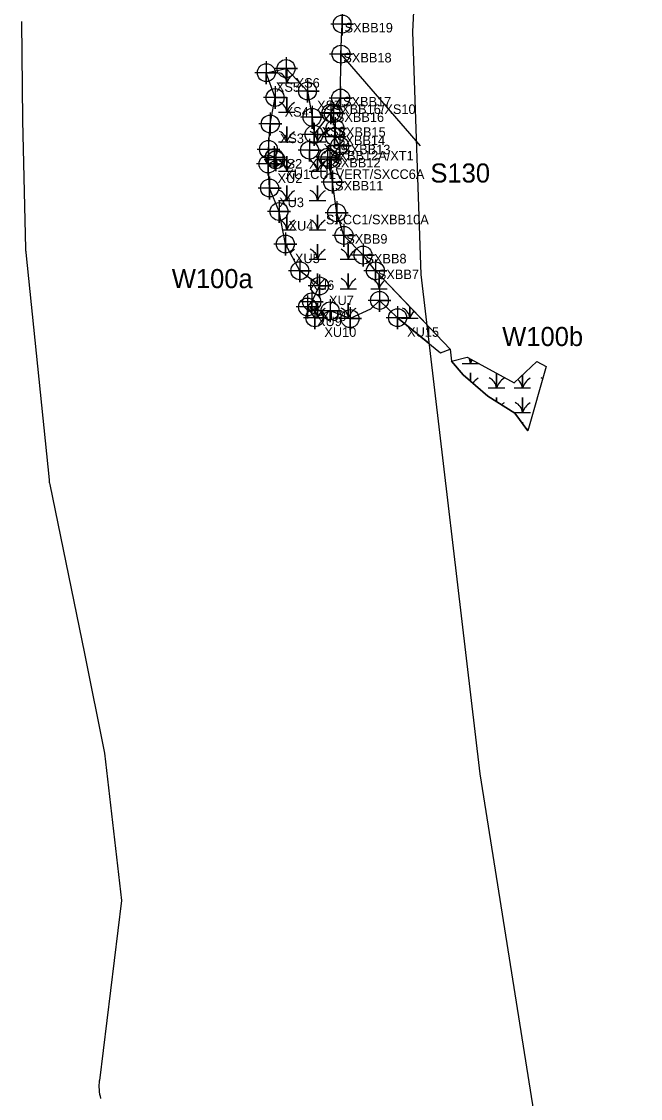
# Model space of a CAD drawing. Extents: x 1253697 to 1278588, y 912189 to 981699.
# Drawn here: x 1268749 to 1269397, y 969005 to 970132 of the extents above; entities that cross this region are included whole.
import ezdxf

# ---------------------------------------------------------------- set-up
doc = ezdxf.new("R2010")
doc.units = 0
for name, color, linetype in [('Default', 7, 'Continuous'), ('Exist Environmental Wetland Boundary', 7, 'Continuous'), ('Exist Environmental Wetland Boundary Cogo Comment', 7, 'Continuous'), ('Exist Environmental Wetland Boundary Cogo Number', 7, 'Continuous'), ('Exist Environmental Wetland Boundary Cogo Point CELL', 7, 'Continuous'), ('Exist Hydro Jurisdictional Stream or Body of Water Mitigable', 7, 'Continuous'), ('Exist Hydro Jurisdictional Stream or Body of Water Mitigable Cogo Comment', 7, 'Continuous'), ('Exist Hydro Jurisdictional Stream or Body of Water Mitigable Cogo Number', 7, 'Continuous'), ('Exist Hydro Jurisdictional Stream or Body of Water Mitigable Cogo Point CELL', 7, 'Continuous'), ('Exist Hydro Swamp or Marsh', 7, 'Continuous')]:
    doc.layers.add(name, color=color, linetype=linetype)

msp = doc.modelspace()

# ---------------------------------------------------------------- linework, layer by layer
at = {"layer": 'Default'}
for p, q in [((1268748.9, 970131.8), (1268749.9, 970028.8)), ((1268748.9, 970131.8), (1268749.9, 970028.8)), ((1269083.5, 970097.7), (1269166.6, 970001.9)), ((1268750, 970028.1), (1268753.1, 969894)), ((1268750, 970028.1), (1268753.1, 969894)), ((1268753.4, 969890.2), (1268777.7, 969652.3)), ((1268753.4, 969890.2), (1268777.7, 969652.3))]:
    msp.add_line(p, q, dxfattribs=at)
for points in [[(1269397.3, 968290), (1269229.4, 969344.4), (1269167.4, 969867.2), (1269158.7, 970121), (1269167.3, 970291.9), (1269169.1, 970315.5)], [(1269397.3, 968290), (1269229.4, 969344.4), (1269167.4, 969867.2), (1269158.7, 970121), (1269167.3, 970291.9), (1269169.1, 970315.5)], [(1268778.5, 969647.3), (1268814.9, 969470.3), (1268835.9, 969366.2), (1268853.5, 969211.8), (1268830.4, 969023.6)], [(1268778.5, 969647.3), (1268814.9, 969470.3), (1268835.9, 969366.2), (1268853.5, 969211.8), (1268830.4, 969023.6)]]:
    msp.add_lwpolyline(points, dxfattribs=at)
for centre, start, end in [((1268799.9, 970029.3), 180.6032, 181.3602), ((1268799.9, 970029.3), 180.6032, 181.3602), ((1268803.1, 969895.2), 181.3602, 185.8348), ((1268803.1, 969895.2), 181.3602, 185.8348), ((1268827.4, 969657.4), 185.8348, 191.6336), ((1268827.4, 969657.4), 185.8348, 191.6336), ((1268880, 969017.5), 172.9863, 194.8089), ((1268880, 969017.5), 172.9863, 194.8089)]:
    msp.add_arc(centre, 50, start, end, dxfattribs=at)
at = {"layer": 'Exist Environmental Wetland Boundary'}
for p, q in [((1269292.2, 969774.1), (1269292.3, 969774.1)), ((1269227.3, 969748.3), (1269227.8, 969748.3))]:
    msp.add_line(p, q, dxfattribs=at)
for points in [[(1269007.1, 969982.8), (1269007.6, 969998), (1269009.4, 970024.6), (1269014.5, 970052.3), (1269005.3, 970078.3), (1269026, 970082.6), (1269048.5, 970059.1), (1269053.2, 970031.6), (1269055.3, 970013.7), (1269073, 970036.3)], [(1269176, 969794.8), (1269142.8, 969821.9), (1269123.9, 969840), (1269114.3, 969830.9), (1269093, 969820.9), (1269072.1, 969829.1), (1269056.1, 969821.8), (1269048.4, 969833.1), (1269052.9, 969838.4), (1269061, 969855.1), (1269040.4, 969871), (1269025.3, 969899), (1269018.6, 969933), (1269008.7, 969957.6), (1269007.1, 969982.8), (1269015.2, 969987.1)], [(1269142.8, 969821.9), (1269187.9, 969785.1), (1269197.8, 969789), (1269119.6, 969870.9)], [(1269210.6, 969774.1), (1269219.2, 969774.1), (1269219.2, 969778.7)], [(1269219.2, 969778.7), (1269219.2, 969774.1), (1269227.7, 969774.1)], [(1269219.2, 969755.4), (1269219.2, 969764.1), (1269219.2, 969755.4)], [(1269237.8, 969748.3), (1269246.4, 969748.3), (1269246.4, 969763.9)], [(1269246.4, 969763.9), (1269246.4, 969748.3), (1269255, 969748.3)], [(1269265, 969748.3), (1269273.6, 969748.3), (1269273.6, 969761.9)], [(1269273.6, 969761.9), (1269273.6, 969748.3), (1269282.2, 969748.3)], [(1269246.4, 969733.9), (1269246.4, 969738.3), (1269246.4, 969733.9)], [(1269265, 969722.5), (1269273.6, 969722.5), (1269273.6, 969738.3), (1269273.6, 969722.5), (1269282.2, 969722.5)], [(1269273.6, 969711), (1269273.6, 969712.5), (1269273.6, 969711)]]:
    msp.add_lwpolyline(points, dxfattribs=at)
msp.add_lwpolyline([(1269199.4, 969776.3), (1269215.7, 969780.6), (1269264.8, 969753.8), (1269288.8, 969775.9), (1269298.4, 969770.9), (1269279.2, 969703.5), (1269265.6, 969721.9), (1269237.2, 969739.7), (1269211.6, 969762.1)], close=True, dxfattribs=at)
for centre, radius, start, end in [((1269206.9, 969773.2), 12.3, 4.1403, 32.0357), ((1269237.4, 969768), 19.2, 149.4542, 161.6222), ((1269237.4, 969742.2), 19.2, 122.1274, 145.031), ((1269234.1, 969747.4), 12.3, 4.1403, 67.535), ((1269264.6, 969742.2), 19.2, 122.1274, 161.6222), ((1269261.3, 969747.4), 12.3, 4.1403, 53.5689), ((1269291.9, 969742.2), 19.2, 122.1274, 161.6222), ((1269288.5, 969747.4), 12.3, 59.7157, 67.535), ((1269264.6, 969716.5), 19.2, 122.1274, 132.5441), ((1269261.3, 969721.6), 12.3, 4.1403, 67.535), ((1269291.9, 969716.5), 19.2, 122.1274, 161.6222), ((1269291.9, 969690.7), 19.2, 128.7859, 134.1878)]:
    msp.add_arc(centre, radius, start, end, dxfattribs=at)
at = {"layer": 'Exist Environmental Wetland Boundary Cogo Point CELL'}
for points in [[(1269005.3, 970090.3), (1269005.3, 970066.3), (1269005.3, 970078.3), (1269017.3, 970078.3), (1268993.3, 970078.3)], [(1269026, 970094.6), (1269026, 970070.6), (1269026, 970082.6), (1269038, 970082.6), (1269014, 970082.6)], [(1269014.5, 970064.3), (1269014.5, 970040.3), (1269014.5, 970052.3), (1269026.5, 970052.3), (1269002.5, 970052.3)], [(1269048.5, 970071.1), (1269048.5, 970047.1), (1269048.5, 970059.1), (1269060.5, 970059.1), (1269036.5, 970059.1)], [(1269053.2, 970043.6), (1269053.2, 970019.6), (1269053.2, 970031.6), (1269065.2, 970031.6), (1269041.2, 970031.6)], [(1269009.4, 970036.6), (1269009.4, 970012.6), (1269009.4, 970024.6), (1269021.4, 970024.6), (1268997.4, 970024.6)], [(1269055.3, 970025.7), (1269055.3, 970001.7), (1269055.3, 970013.7), (1269067.3, 970013.7), (1269043.3, 970013.7)], [(1269007.6, 970010), (1269007.6, 969986), (1269007.6, 969998), (1269019.6, 969998), (1268995.6, 969998)], [(1269050.6, 970009.2), (1269050.6, 969985.2), (1269050.6, 969997.2), (1269062.6, 969997.2), (1269038.6, 969997.2)], [(1269007.1, 969994.8), (1269007.1, 969970.8), (1269007.1, 969982.8), (1269019.1, 969982.8), (1268995.1, 969982.8)], [(1269013.5, 970001.5), (1269013.5, 969977.5), (1269013.5, 969989.5), (1269025.5, 969989.5), (1269001.5, 969989.5)], [(1269015.2, 969999.1), (1269015.2, 969975.1), (1269015.2, 969987.1), (1269027.2, 969987.1), (1269003.2, 969987.1)], [(1269008.7, 969969.6), (1269008.7, 969945.6), (1269008.7, 969957.6), (1269020.7, 969957.6), (1268996.7, 969957.6)], [(1269018.6, 969945), (1269018.6, 969921), (1269018.6, 969933), (1269030.6, 969933), (1269006.6, 969933)], [(1269025.3, 969911), (1269025.3, 969887), (1269025.3, 969899), (1269037.3, 969899), (1269013.3, 969899)], [(1269040.4, 969883), (1269040.4, 969859), (1269040.4, 969871), (1269052.4, 969871), (1269028.4, 969871)], [(1269061, 969867.1), (1269061, 969843.1), (1269061, 969855.1), (1269073, 969855.1), (1269049, 969855.1)], [(1269052.9, 969850.4), (1269052.9, 969826.4), (1269052.9, 969838.4), (1269064.9, 969838.4), (1269040.9, 969838.4)], [(1269123.9, 969852), (1269123.9, 969828), (1269123.9, 969840), (1269135.9, 969840), (1269111.9, 969840)], [(1269048.4, 969845.1), (1269048.4, 969821.1), (1269048.4, 969833.1), (1269060.4, 969833.1), (1269036.4, 969833.1)], [(1269072.1, 969841.1), (1269072.1, 969817.1), (1269072.1, 969829.1), (1269084.1, 969829.1), (1269060.1, 969829.1)], [(1269056.1, 969833.8), (1269056.1, 969809.8), (1269056.1, 969821.8), (1269068.1, 969821.8), (1269044.1, 969821.8)], [(1269093, 969832.9), (1269093, 969808.9), (1269093, 969820.9), (1269105, 969820.9), (1269081, 969820.9)], [(1269142.8, 969833.9), (1269142.8, 969809.9), (1269142.8, 969821.9), (1269154.8, 969821.9), (1269130.8, 969821.9)]]:
    msp.add_lwpolyline(points, dxfattribs=at)
for centre in [(1269005.3, 970078.3), (1269026, 970082.6), (1269014.5, 970052.3), (1269048.5, 970059.1), (1269053.2, 970031.6), (1269009.4, 970024.6), (1269055.3, 970013.7), (1269007.6, 969998), (1269050.6, 969997.2), (1269013.5, 969989.5), (1269015.2, 969987.1), (1269007.1, 969982.8), (1269008.7, 969957.6), (1269018.6, 969933), (1269025.3, 969899), (1269040.4, 969871), (1269061, 969855.1), (1269052.9, 969838.4), (1269123.9, 969840), (1269048.4, 969833.1), (1269072.1, 969829.1), (1269056.1, 969821.8), (1269093, 969820.9), (1269142.8, 969821.9)]:
    msp.add_circle(centre, 9.38, dxfattribs=at)
at = {"layer": 'Exist Hydro Jurisdictional Stream or Body of Water Mitigable'}
for points in [[(1269173.7, 969814.3), (1269119.6, 969870.9), (1269106.6, 969887.4), (1269086.6, 969908), (1269079, 969931.7), (1269074.8, 969963.8), (1269071.9, 969987.9), (1269082.2, 970001.7), (1269076.7, 970011.2), (1269077.3, 970019.9), (1269073, 970036.3), (1269083.1, 970051.7), (1269083.5, 970097.7), (1269084.8, 970129.2), (1269085.3, 970162.5)], [(1269119.6, 969870.9), (1269197.8, 969789), (1269199.4, 969776.3), (1269211.6, 969762.1), (1269237.2, 969739.7), (1269265.6, 969721.9), (1269279.2, 969703.5)]]:
    msp.add_lwpolyline(points, dxfattribs=at)
at = {"layer": 'Exist Hydro Jurisdictional Stream or Body of Water Mitigable Cogo Point CELL'}
for points in [[(1269084.8, 970141.2), (1269084.8, 970117.2), (1269084.8, 970129.2), (1269096.8, 970129.2), (1269072.8, 970129.2)], [(1269083.5, 970109.7), (1269083.5, 970085.7), (1269083.5, 970097.7), (1269095.5, 970097.7), (1269071.5, 970097.7)], [(1269083.1, 970063.7), (1269083.1, 970039.7), (1269083.1, 970051.7), (1269095.1, 970051.7), (1269071.1, 970051.7)], [(1269073, 970048.3), (1269073, 970024.3), (1269073, 970036.3), (1269085, 970036.3), (1269061, 970036.3)], [(1269075.6, 970047.5), (1269075.6, 970023.5), (1269075.6, 970035.5), (1269087.6, 970035.5), (1269063.6, 970035.5)], [(1269077.3, 970031.9), (1269077.3, 970007.9), (1269077.3, 970019.9), (1269089.3, 970019.9), (1269065.3, 970019.9)], [(1269076.7, 970023.2), (1269076.7, 969999.2), (1269076.7, 970011.2), (1269088.7, 970011.2), (1269064.7, 970011.2)], [(1269082.2, 970013.7), (1269082.2, 969989.7), (1269082.2, 970001.7), (1269094.2, 970001.7), (1269070.2, 970001.7)], [(1269069.5, 970001.8), (1269069.5, 969977.8), (1269069.5, 969989.8), (1269081.5, 969989.8), (1269057.5, 969989.8)], [(1269071.9, 969999.9), (1269071.9, 969975.9), (1269071.9, 969987.9), (1269083.9, 969987.9), (1269059.9, 969987.9)], [(1269074.8, 969975.8), (1269074.8, 969951.8), (1269074.8, 969963.8), (1269086.8, 969963.8), (1269062.8, 969963.8)], [(1269079, 969943.7), (1269079, 969919.7), (1269079, 969931.7), (1269091, 969931.7), (1269067, 969931.7)], [(1269086.6, 969920), (1269086.6, 969896), (1269086.6, 969908), (1269098.6, 969908), (1269074.6, 969908)], [(1269106.6, 969899.4), (1269106.6, 969875.4), (1269106.6, 969887.4), (1269118.6, 969887.4), (1269094.6, 969887.4)], [(1269119.6, 969882.9), (1269119.6, 969858.9), (1269119.6, 969870.9), (1269131.6, 969870.9), (1269107.6, 969870.9)]]:
    msp.add_lwpolyline(points, dxfattribs=at)
for centre in [(1269084.8, 970129.2), (1269083.5, 970097.7), (1269083.1, 970051.7), (1269073, 970036.3), (1269075.6, 970035.5), (1269077.3, 970019.9), (1269076.7, 970011.2), (1269082.2, 970001.7), (1269069.5, 969989.8), (1269071.9, 969987.9), (1269074.8, 969963.8), (1269079, 969931.7), (1269086.6, 969908), (1269106.6, 969887.4), (1269119.6, 969870.9)]:
    msp.add_circle(centre, 9.38, dxfattribs=at)
at = {"layer": 'Exist Hydro Swamp or Marsh'}
for p, q in [((1269050.3, 970036.9), (1269052.3, 970036.9)), ((1269082.5, 969913.8), (1269084.8, 969913.8)), ((1269033.9, 969883), (1269035.3, 969883)), ((1269059.6, 969852.2), (1269067.5, 969852.2)), ((1269091.7, 969821.5), (1269094.1, 969821.5))]:
    msp.add_line(p, q, dxfattribs=at)
for points in [[(1269018.1, 970067.7), (1269026.7, 970067.7), (1269026.7, 970081.8)], [(1269026.7, 970081.8), (1269026.7, 970067.7), (1269035.3, 970067.7)], [(1269018.1, 970036.9), (1269026.7, 970036.9), (1269026.7, 970052.7), (1269026.7, 970036.9), (1269035.3, 970036.9)], [(1269018.1, 970006.1), (1269026.7, 970006.1), (1269026.7, 970021.9), (1269026.7, 970006.1), (1269035.3, 970006.1)], [(1269050.3, 970006.1), (1269058.9, 970006.1), (1269058.9, 970018.4)], [(1269058.9, 970018.4), (1269058.9, 970006.1), (1269067.5, 970006.1)], [(1269018.1, 969975.4), (1269026.7, 969975.4), (1269026.7, 969991.1), (1269026.7, 969975.4), (1269035.3, 969975.4)], [(1269050.3, 969975.4), (1269058.9, 969975.4), (1269058.9, 969991.1), (1269058.9, 969975.4), (1269067.5, 969975.4)], [(1269018.1, 969944.6), (1269026.7, 969944.6), (1269026.7, 969960.4), (1269026.7, 969944.6), (1269035.3, 969944.6)], [(1269050.3, 969944.6), (1269058.9, 969944.6), (1269058.9, 969960.4), (1269058.9, 969944.6), (1269067.5, 969944.6)], [(1269022.4, 969913.8), (1269026.7, 969913.8), (1269026.7, 969929.6), (1269026.7, 969913.8), (1269035.3, 969913.8)], [(1269050.3, 969913.8), (1269058.9, 969913.8), (1269058.9, 969929.6), (1269058.9, 969913.8), (1269067.5, 969913.8)], [(1269026.7, 969896.3), (1269026.7, 969898.8), (1269026.7, 969896.3)], [(1269050.3, 969883), (1269058.9, 969883), (1269058.9, 969898.8), (1269058.9, 969883), (1269067.5, 969883)], [(1269082.5, 969883), (1269091.1, 969883), (1269091.1, 969898.8), (1269091.1, 969883), (1269099.7, 969883)], [(1269058.9, 969856.7), (1269058.9, 969868), (1269058.9, 969856.7)], [(1269082.5, 969852.2), (1269091.1, 969852.2), (1269091.1, 969868), (1269091.1, 969852.2), (1269099.7, 969852.2)], [(1269114.7, 969852.2), (1269123.4, 969852.2), (1269123.4, 969867)], [(1269123.4, 969867), (1269123.4, 969852.2), (1269132, 969852.2)], [(1269058.9, 969823.1), (1269058.9, 969837.2), (1269058.9, 969823.1)], [(1269091.1, 969821.7), (1269091.1, 969837.2), (1269091.1, 969821.7)], [(1269147, 969821.5), (1269155.6, 969821.5), (1269155.6, 969833.3)], [(1269155.6, 969833.3), (1269155.6, 969821.5), (1269164.2, 969821.5)]]:
    msp.add_lwpolyline(points, dxfattribs=at)
for centre, radius, start, end in [((1269014.5, 970066.8), 12.3, 4.1403, 67.535), ((1269045, 970061.6), 19.2, 131.4132, 161.6222), ((1269014.5, 970036), 12.3, 4.1403, 67.535), ((1269045, 970030.9), 19.2, 122.1274, 161.6222), ((1269014.5, 970005.3), 12.3, 4.1403, 67.535), ((1269045, 970000.1), 19.2, 122.1274, 161.6222), ((1269046.7, 970005.3), 12.3, 46.0042, 67.535), ((1269077.2, 970000.1), 19.2, 122.1274, 161.6222), ((1269046.7, 970005.3), 12.3, 4.1403, 44.674), ((1269014.5, 969974.5), 12.3, 4.1403, 67.535), ((1269045, 969969.3), 19.2, 122.1274, 161.6222), ((1269046.7, 969974.5), 12.3, 4.1403, 67.535), ((1269077.2, 969969.3), 19.2, 122.1274, 161.6222), ((1269014.5, 969943.7), 12.3, 4.1403, 67.535), ((1269045, 969938.5), 19.2, 122.1274, 161.6222), ((1269046.7, 969943.7), 12.3, 4.1403, 67.535), ((1269077.2, 969938.5), 19.2, 122.1274, 161.6222), ((1269014.5, 969912.9), 12.3, 4.1403, 60.802), ((1269045, 969907.7), 19.2, 122.1274, 161.6222), ((1269046.7, 969912.9), 12.3, 4.1403, 67.535), ((1269077.2, 969907.7), 19.2, 122.1274, 161.6222), ((1269045, 969877), 19.2, 122.1274, 139.2433), ((1269046.7, 969882.1), 12.3, 4.1403, 67.535), ((1269077.2, 969877), 19.2, 122.1274, 161.6222), ((1269078.9, 969882.1), 12.3, 4.1403, 67.535), ((1269109.4, 969877), 19.2, 122.1274, 161.6222), ((1269046.7, 969851.4), 12.3, 34.946, 67.535), ((1269077.2, 969846.2), 19.2, 122.1274, 150.7375), ((1269078.9, 969851.4), 12.3, 4.1403, 67.535), ((1269109.4, 969846.2), 19.2, 122.1274, 161.6222), ((1269111.1, 969851.4), 12.3, 4.1403, 67.535), ((1269141.6, 969846.2), 19.2, 130.091, 161.6222), ((1269046.7, 969820.6), 12.3, 11.4282, 67.535), ((1269077.2, 969815.4), 19.2, 122.1274, 155.1923), ((1269078.9, 969820.6), 12.3, 5.178, 67.535), ((1269109.4, 969815.4), 19.2, 122.1274, 161.024), ((1269143.3, 969820.6), 12.3, 4.1403, 67.535), ((1269173.8, 969815.4), 19.2, 136.2314, 161.6222)]:
    msp.add_arc(centre, radius, start, end, dxfattribs=at)

# ---------------------------------------------------------------- texts
at = {"layer": 'Exist Environmental Wetland Boundary'}
msp.add_text('W100b', height=20, dxfattribs=at).set_placement((1269252.4, 969792.2))
at = {"layer": 'Exist Environmental Wetland Boundary Cogo Comment'}
for s, p in [('XS6', (1269036, 970062.6)), ('XS5', (1269015.3, 970058.3)), ('XS4', (1269024.5, 970032.3)), ('XS7', (1269058.5, 970039.1)), ('XS8', (1269063.2, 970011.6)), ('XS3', (1269019.4, 970004.6)), ('XS9', (1269065.3, 969993.7)), ('XS2', (1269017.6, 969978)), ('XT3', (1269050.1, 969978)), ('XT2', (1269060.6, 969977.2)), ('XU2', (1269017.1, 969962.8)), ('XU1CULVERT/SXCC6A', (1269025.2, 969967.1)), ('XU3', (1269018.7, 969937.6)), ('XU4', (1269028.6, 969913)), ('XU5', (1269035.3, 969879)), ('XU6', (1269050.4, 969851)), ('XU7', (1269071, 969835.1)), ('XU8', (1269062.9, 969818.4)), ('XU9', (1269058.4, 969813.1)), ('XU10', (1269066.1, 969801.8)), ('XU15', (1269152.8, 969801.9))]:
    msp.add_text(s, height=10, dxfattribs=at).set_placement(p)
at = {"layer": 'Exist Environmental Wetland Boundary Cogo Number'}
msp.add_text('W100a', height=20, dxfattribs=at).set_placement((1268906.3, 969852.8))
at = {"layer": 'Exist Hydro Jurisdictional Stream or Body of Water Mitigable Cogo Comment'}
for s, p in [('SXBB19', (1269087.3, 970120.4)), ('SXBB18', (1269086, 970089)), ('SXBB17', (1269085.6, 970043)), ('SXBB16/XS10', (1269074.7, 970035.1)), ('SXBB16', (1269078.1, 970026.8)), ('SXBB15', (1269079.8, 970011.2)), ('SXBB14', (1269079.2, 970002.5)), ('SXBB12A/XT1', (1269072, 969986.5)), ('SXBB13', (1269084.7, 969992.9)), ('SXBB12', (1269074.4, 969979.1)), ('SXBB11', (1269077.3, 969955)), ('SXCC1/SXBB10A', (1269067.7, 969919.6)), ('SXBB9', (1269089.1, 969899.3)), ('SXBB8', (1269109.1, 969878.7)), ('SXBB7', (1269122.1, 969862.2))]:
    msp.add_text(s, height=10, dxfattribs=at).set_placement(p)
at = {"layer": 'Exist Hydro Jurisdictional Stream or Body of Water Mitigable Cogo Number'}
msp.add_text('S130', height=20, dxfattribs=at).set_placement((1269177.2, 969963.3))

doc.saveas('drawing.dxf')
